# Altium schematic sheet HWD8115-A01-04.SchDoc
size A3; SheetNumber: 0; SheetTotal: 0; PageSetup: Record=PageOptions¦CenterHorizontal=True¦CenterVertical=True¦PrintScale=0.71¦XCorrection=1.00¦YCorrection=1.00¦PrintKind=0¦BorderSize=5000000¦LeftOffset=0¦BottomOffset=0¦Orientation=2¦PaperLength=1000¦PaperWidth=1000¦Scale=100¦PaperSource=7¦PrintQuality=-3¦MediaType=1¦DitherType=10¦PrintScaleMode=1¦PaperKind=A4¦PaperIndex=9
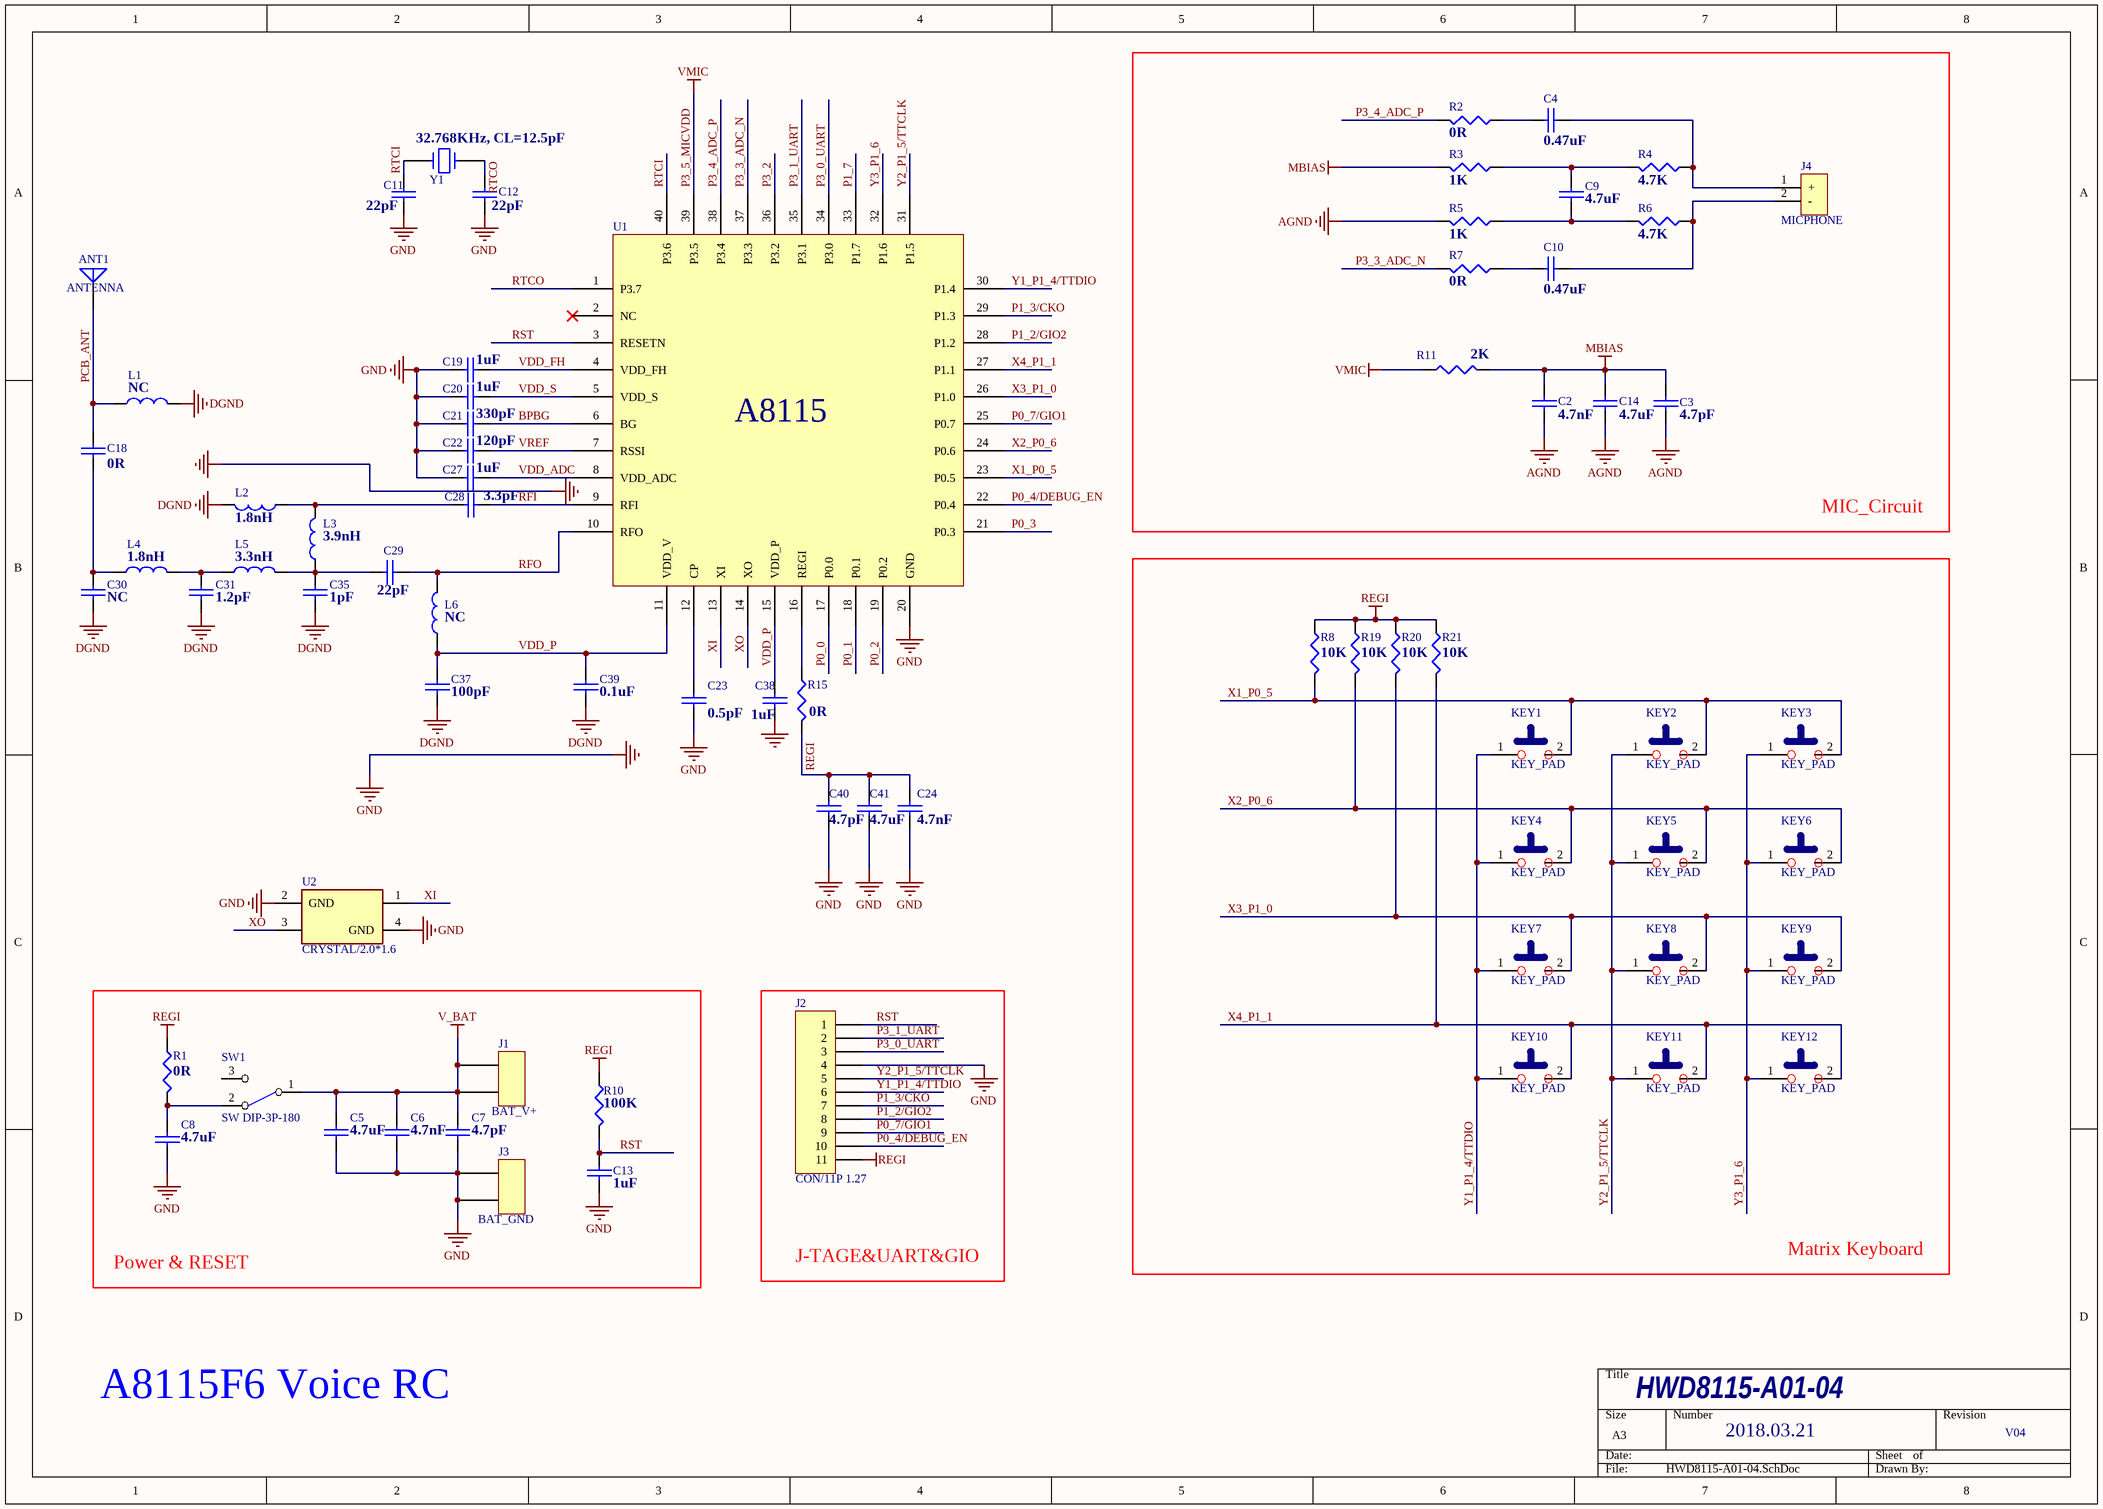
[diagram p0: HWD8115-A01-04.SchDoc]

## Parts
ANT1  ANTENNA  [ANT_Bit]
C2  4.7nF  [0402]
C3  4.7pF  [0402]
C4  0.47uF  [0402]
C5  4.7uF  [0603]
C6  4.7nF  [0402]
C7  4.7pF  [0402]
C8  4.7uF  [0603]
C9  4.7uF  [0402]
C10  0.47uF  [0402]
C11  22pF  [0402]
C12  22pF  [0402]
C13  1uF  [0402]
C14  4.7uF  [0603]
C18  0R  [0402]
C19  1uF  [0402]
C20  1uF  [0402]
C21  330pF  [0402]
C22  120pF  [0402]
C23  0.5pF  [0402]
C24  4.7nF  [0402]
C27  1uF  [0402]
C28  3.3pF  [0402]
C29  22pF  [0402]
C30  NC  [0402]
C31  1.2pF  [0402]
C35  1pF  [0402]
C37  100pF  [0402]
C38  1uF  [0402]
C39  0.1uF  [0402]
C40  4.7pF  [0402]
C41  4.7uF  [0603]
J1  BAT_V+  [BAT_PAD - duplicate1]
J2  CON/11P 1.27  [HDR11_1.27]
J3  BAT_GND  [BAT_PAD - duplicate1]
J4  MICPHONE  [MIC PHONE]
KEY1  KEY_PAD  [SW-4]
KEY2  KEY_PAD  [SW-4]
KEY3  KEY_PAD  [SW-4]
KEY4  KEY_PAD  [SW-4]
KEY5  KEY_PAD  [SW-4]
KEY6  KEY_PAD  [SW-4]
KEY7  KEY_PAD  [SW-4]
KEY8  KEY_PAD  [SW-4]
KEY9  KEY_PAD  [SW-4]
KEY10  KEY_PAD  [SW-4]
KEY11  KEY_PAD  [SW-4]
KEY12  KEY_PAD  [SW-4]
L1  NC  [0402]
L2  1.8nH  [0402]
L3  3.9nH  [0402]
L4  1.8nH  [0402]
L5  3.3nH  [0402]
L6  NC  [0402]
R1  0R  [0603]
R2  0R  [0402]
R3  1K  [0402]
R4  4.7K  [0402]
R5  1K  [0402]
R6  4.7K  [0402]
R7  0R  [0402]
R8  10K  [0402]
R10  100K  [0402]
R11  2K  [0402]
R15  0R  [0402]
R19  10K  [0402]
R20  10K  [0402]
R21  10K  [0402]
SW1  SW DIP-3P-180  [SW3-2]
U1  (no value)  [A8153]
U2  CRYSTAL/2.0*1.6  [XTAL_2.0*1.6]
Y1  32.768KHz, CL=12.5pF  [XTAL\32.768K\SMD]

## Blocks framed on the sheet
MIC_Circuit: C2-C4 C9 C10 C14 J4 R2-R7 R11
Matrix Keyboard: KEY1-KEY12 R8 R19-R21
Power & RESET: C5-C8 C13 J1 J3 R1 R10 SW1
J-TAGE&UART&GIO: J2

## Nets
AGND: C2.2 C3.2 C14.2 R5.1
DGND: C30.1 C31.1 C35.2 C37.2 C39.2 L1.2 L2.2
GND: C5.2 C6.2 C7.2 C8.2 C11.2 C12.2 C13.2 C19.2 C20.2 C21.2 C22.2 C23.2 C24.2 C27.2 C38.2 C40.2 C41.2 J2.4 J3.1 J3.2 U1.20(GND) U2.2(GND) U2.4(GND)
MBIAS: C2.1 C3.1 C14.1 R3.1 R11.1
P3_5_MICVDD: R11.2 U1.39(P3.5)  [also labelled VMIC]
REGI: C24.1 C40.1 C41.1 J2.11 R1.1 R8.1 R10.1 R15.1 R19.1 R20.1 R21.1
V_BAT: C5.1 C6.1 C7.1 J1.1 J1.2 SW1.1(COMMON)
BPBG: C21.1 U1.6(BG)
P0_0: U1.17(P0.0)
P0_1: U1.18(P0.1)
P0_2: U1.19(P0.2)
P0_3: U1.21(P0.3)
P0_4/DEBUG_EN: J2.10 U1.22(P0.4)
P0_7/GIO1: J2.9 U1.25(P0.7)
P1_2/GIO2: J2.8 U1.28(P1.2)
P1_3/CKO: J2.7 U1.29(P1.3)
P1_7: U1.33(P1.7)
P3_0_UART: J2.3 U1.34(P3.0)
P3_1_UART: J2.2 U1.35(P3.1)
P3_2: U1.36(P3.2)
P3_3_ADC_N: R7.1 U1.37(P3.3)
P3_4_ADC_P: R2.1 U1.38(P3.4)
PCB_ANT: ANT1.1(A) C18.1 L1.1
RFI: C28.1 U1.9(RFI)
RFO: C29.1 L6.2 U1.10(RFO)
RST: C13.1 J2.1 R10.2 U1.3(RESETN)
RTCI: C11.1 U1.40(P3.6) Y1.1
RTCO: C12.1 U1.1(P3.7) Y1.2
VDD_ADC: C27.1 U1.8(VDD_ADC)
VDD_FH: C19.1 U1.4(VDD_FH)
VDD_P: C37.1 C38.1 C39.1 L6.1 U1.11(VDD_V) U1.15(VDD_P)
VDD_S: C20.1 U1.5(VDD_S)
VREF: C22.1 U1.7(RSSI)
X1_P0_5: KEY1.2 KEY2.2 KEY3.2 R8.2 U1.23(P0.5)
X2_P0_6: KEY4.2 KEY5.2 KEY6.2 R19.2 U1.24(P0.6)
X3_P1_0: KEY7.2 KEY8.2 KEY9.2 R20.2 U1.26(P1.0)
X4_P1_1: KEY10.2 KEY11.2 KEY12.2 R21.2 U1.27(P1.1)
XI: U1.13(XI) U2.1
XO: U1.14(XO) U2.3
Y1_P1_4/TTDIO: J2.6 KEY1.1 KEY4.1 KEY7.1 KEY10.1 U1.30(P1.4)
Y2_P1_5/TTCLK: J2.5 KEY2.1 KEY5.1 KEY8.1 KEY11.1 U1.31(P1.5)
Y3_P1_6: KEY3.1 KEY6.1 KEY9.1 KEY12.1 U1.32(P1.6)
NetC4_1: C4.1 R2.2
NetC4_2: C4.2 J4.1(+) R4.2
NetC8_1: C8.1 R1.2 SW1.2(NC)
NetC9_1: C9.1 R3.2 R4.1
NetC9_2: C9.2 R5.2 R6.1
NetC10_1: C10.1 R7.2
NetC10_2: C10.2 J4.2(-) R6.2
NetC18_2: C18.2 C30.2 L4.1
NetC23_1: C23.1 U1.12(CP)
NetC28_2: C28.2 L2.1 L3.2
NetC29_2: C29.2 C35.1 L3.1 L5.2
NetC31_2: C31.2 L4.2 L5.1
NetR15_2: R15.2 U1.16(REGI)

Not connected (* = marked no-connect by the designer): SW1 3(NO); U1 2(NC)*

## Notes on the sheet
- A8115F6 Voice RC
- HWD8115-A01-04
- 2018.03.21
- V04

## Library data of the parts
C2-C10 C14 C18-C24 C27-C31 C35 C37-C41 = CAP
C11 C12 = C/0603: Chip C
C13 = C/0402: Chip C
J1 J3 = BAT_PAD
J2 = CON/11P 1.27: Hole 23mil
L1-L6 = L/0402: Chip L
R1 R8 R19-R21 = RES1
R2-R7 R10 R11 R15 = R/0603: Chip  R
U1 = A8115
U2 = CRYSTAL/5*3.2
Y1 = CRYSTAL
